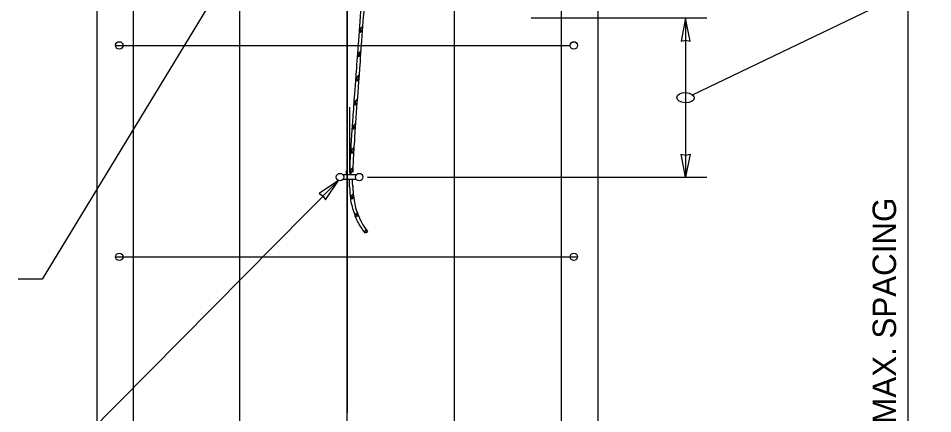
# Model space of a CAD drawing. Extents: x 99862 to 104211, y 98939 to 105076.
# Drawn here: x 101927 to 102551, y 100755 to 101026 of the extents above; entities that cross this region are included whole.
import ezdxf

# ---------------------------------------------------------------- set-up
doc = ezdxf.new("R2010")
doc.units = 0
for name, color, linetype in [('Level 10', 7, 'Continuous'), ('Level 15', 7, 'Continuous'), ('Level 18', 7, 'Continuous'), ('Level 2', 7, 'Continuous'), ('Level 20', 7, 'Continuous'), ('Level 5', 7, 'Continuous'), ('Level 7', 7, 'Continuous')]:
    doc.layers.add(name, color=color, linetype=linetype)

msp = doc.modelspace()

# ---------------------------------------------------------------- linework, layer by layer
at = {"layer": 'Level 10'}
for p, q in [((102078.31, 100424.94), (102078.31, 101353.23)), ((102224.89, 100424.94), (102224.89, 101353.23)), ((102005.44, 101153.73), (102005.44, 100424.94)), ((102151.6, 101153.73), (102151.6, 100755.98)), ((102297.76, 101153.73), (102297.76, 100424.94)), ((101993.44, 101007.17), (102303.77, 101007.17)), ((101993.44, 100862.63), (102308.86, 100862.63))]:
    msp.add_line(p, q, dxfattribs=at)
for centre in [(101995.98, 101007.17), (102306.31, 101007.17), (101995.98, 100862.63), (102306.31, 100862.63)]:
    msp.add_circle(centre, 2.54, dxfattribs=at)
at = {"layer": 'Level 15'}
for p, q in [((102151.6, 100419.56), (102151.6, 101466.64)), ((102534.31, 101153.73), (102534.31, 100429.01)), ((102387.34, 100973.37), (102660, 101104.51)), ((102070.77, 101057.38), (101943.35, 100847.44)), ((102397.06, 101025.68), (102277.16, 101025.68)), ((102382.59, 101025.68), (102382.59, 100917.11)), ((102153.51, 100920.37), (102153.51, 100964.95)), ((102145.73, 100914.78), (101943.35, 100710.27)), ((102165.54, 100917.11), (102397.06, 100917.11)), ((101943.35, 100847.44), (101927.06, 100847.44))]:
    msp.add_line(p, q, dxfattribs=at)
msp.add_lwpolyline([(102145.73, 100914.78), (102132.39, 100905.9), (102135.08, 100904.22), (102136.73, 100901.52)], close=True, dxfattribs=at)
at = {"layer": 'Level 18'}
for p, q in [((102162.13, 101020.09), (102160.77, 101018.73)), ((102160.57, 101015.97), (102161.93, 101017.33)), ((102159.35, 100999.4), (102160.71, 101000.76)), ((102160.91, 101003.52), (102159.55, 101002.16)), ((102158.13, 100982.82), (102159.49, 100984.18)), ((102159.69, 100986.94), (102158.33, 100985.58)), ((102158.47, 100970.37), (102157.12, 100969.02)), ((102156.92, 100966.26), (102158.27, 100967.62)), ((102155.74, 100949.73), (102157.1, 100951.08)), ((102157.29, 100953.83), (102155.93, 100952.48)), ((102154.68, 100933.31), (102156.02, 100934.65)), ((102154.68, 100933.31), (102156.02, 100934.65)), ((102156.18, 100937.37), (102154.84, 100936.03)), ((102153.76, 100919.35), (102155.09, 100920.69)), ((102155.26, 100923.41), (102153.92, 100922.07)), ((102155.76, 100905.62), (102154.61, 100904.48)), ((102154.9, 100902.2), (102156.01, 100903.32)), ((102158.42, 100892.93), (102157.44, 100891.95)), ((102158.17, 100890.12), (102159.13, 100891.08)), ((102164.63, 100881.23), (102163.73, 100880.33)), ((102164.52, 100879.23), (102165.54, 100879.97))]:
    msp.add_line(p, q, dxfattribs=at)
for points in [[(102156.02, 100934.65), (102156.02, 100934.65)], [(102155.09, 100920.69), (102155.09, 100920.69)], [(102155.76, 100905.62), (102155.76, 100905.62)], [(102159.13, 100891.08), (102159.13, 100891.08)], [(102164.63, 100881.23), (102164.63, 100881.23)]]:
    msp.add_lwpolyline(points, dxfattribs=at)
for points, degree in [([(102161.93, 101017.33), (102161.98, 101018.13), (102162.04, 101018.93), (102162.11, 101019.85), (102162.12, 101019.97), (102162.13, 101020.09)], 3), ([(102160.77, 101018.73), (102160.7, 101017.81), (102160.63, 101016.89), (102160.57, 101015.97)], 2), ([(102159.55, 101002.16), (102159.48, 101001.23), (102159.42, 101000.31), (102159.35, 100999.4)], 2), ([(102160.71, 101000.76), (102160.78, 101001.67), (102160.84, 101002.6), (102160.91, 101003.52)], 2), ([(102158.33, 100985.58), (102158.26, 100984.66), (102158.19, 100983.74), (102158.13, 100982.82)], 2), ([(102159.49, 100984.18), (102159.55, 100985.1), (102159.62, 100986.02), (102159.69, 100986.94)], 2), ([(102158.27, 100967.62), (102158.34, 100968.53), (102158.41, 100969.45), (102158.47, 100970.37)], 2), ([(102157.12, 100969.02), (102157.05, 100968.09), (102156.98, 100967.17), (102156.92, 100966.26)], 2), ([(102155.93, 100952.48), (102155.87, 100951.55), (102155.81, 100950.63), (102155.74, 100949.73)], 2), ([(102157.1, 100951.08), (102157.16, 100951.99), (102157.22, 100952.91), (102157.29, 100953.83)], 2), ([(102154.84, 100936.03), (102154.78, 100935.11), (102154.73, 100934.2), (102154.68, 100933.31)], 2), ([(102156.02, 100934.65), (102156.07, 100935.54), (102156.12, 100936.45), (102156.18, 100937.37)], 2), ([(102153.92, 100922.07), (102153.86, 100921.14), (102153.81, 100920.24), (102153.76, 100919.35)], 2), ([(102155.09, 100920.69), (102155.15, 100921.58), (102155.2, 100922.48), (102155.26, 100923.41)], 2), ([(102154.61, 100904.48), (102154.69, 100903.7), (102154.79, 100902.94), (102154.9, 100902.2)], 2), ([(102156.01, 100903.32), (102155.97, 100903.63), (102155.93, 100903.95), (102155.85, 100904.71), (102155.8, 100905.16), (102155.76, 100905.62)], 3), ([(102157.44, 100891.95), (102157.67, 100891.34), (102157.91, 100890.73), (102158.17, 100890.12)], 2), ([(102159.13, 100891.08), (102159.08, 100891.2), (102159.03, 100891.32), (102158.79, 100891.93), (102158.6, 100892.43), (102158.42, 100892.93)], 3), ([(102163.73, 100880.33), (102163.99, 100879.97), (102164.25, 100879.6), (102164.52, 100879.23)], 2), ([(102165.54, 100879.97), (102165.23, 100880.4), (102164.93, 100880.82), (102164.63, 100881.23)], 2)]:
    msp.add_open_spline(points, degree=degree, dxfattribs=at)
at = {"layer": 'Level 2'}
for p, q in [((101980.6, 101178.16), (101980.6, 100396.44)), ((102322.6, 101178.16), (102322.6, 100396.44))]:
    msp.add_line(p, q, dxfattribs=at)
at = {"layer": 'Level 5'}
for p, q in [((102157.75, 100918.66), (102148.75, 100918.66)), ((102148.75, 100915.64), (102157.75, 100915.64))]:
    msp.add_line(p, q, dxfattribs=at)
for centre in [(102146.68, 100917.15), (102159.81, 100917.15)]:
    msp.add_circle(centre, 2.55, dxfattribs=at)
for points, degree in [([(102166.16, 101111.36), (102163.8, 101072.35), (102160.86, 101032.23), (102157.1, 100981.24), (102155.95, 100965.78), (102154.81, 100949.5), (102154.6, 100946.4), (102154.21, 100940.52), (102154.03, 100937.74), (102153.56, 100929.82), (102153.33, 100925.11), (102153.23, 100920.86)], 3), ([(102168.32, 101111.22), (102166.44, 101080.21), (102164.2, 101048.5), (102160, 100990.96), (102158.04, 100965.13), (102156.09, 100936.24), (102155.6, 100928.27), (102155.4, 100921.18), (102155.39, 100920.88), (102155.39, 100920.58)], 3), ([(102151.06, 100918.66), (102151.1, 100920.18), (102151.19, 100921.71)], 2), ([(102153.67, 100918.66), (102153.69, 100919.62), (102153.73, 100920.59), (102153.79, 100921.57)], 2), ([(102153.25, 100910.58), (102153.09, 100913.09), (102153.09, 100915.64)], 2), ([(102155.42, 100910.71), (102155.31, 100912.34), (102155.26, 100913.99), (102155.25, 100915.64)], 2), ([(102153.25, 100910.68), (102153.51, 100903.84), (102154.35, 100898.29), (102157.7, 100888.14), (102160.22, 100883.56), (102163.78, 100878.69)], 3), ([(102155.41, 100911.08), (102155.5, 100908.64), (102155.66, 100906.39), (102156.45, 100899.42), (102157.44, 100895.31), (102160.54, 100887.56), (102162.66, 100883.9), (102165.54, 100879.97)], 3)]:
    msp.add_open_spline(points, degree=degree, dxfattribs=at)
at = {"layer": 'Level 7'}
for points in [[(102382.59, 101025.68), (102379.5, 101009.96), (102382.59, 101010.68), (102385.67, 101009.96)], [(102382.59, 100917.11), (102379.5, 100932.83), (102382.59, 100932.11), (102385.67, 100932.83)]]:
    msp.add_lwpolyline(points, close=True, dxfattribs=at)
msp.add_ellipse((102382.59, 100971.39), major_axis=(-5.99, 0.25), ratio=0.57735, dxfattribs=at)

# ---------------------------------------------------------------- texts
at = {"layer": 'Level 20'}
msp.add_text('#5 @ 1\' - 0" MAX. SPACING', height=16, rotation=90, dxfattribs=at).set_placement((102526.31, 100630.68))

doc.saveas('drawing.dxf')
